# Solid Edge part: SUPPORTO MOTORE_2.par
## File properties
Subject: SUPPORTO MOTORE_2
Author: f_grande
Template: Normal.par
Last saved by: f_grande
Revision: 5
Application: Solid Edge
Material: Alluminio, 1060
Stile della faccia: Alluminio
Stile di riempimento: ANSI38(Alluminio)
Stile virtuale: Alluminio lucidato
Coef. of Thermal Exp: 0.0
Thermal Conductivity: 221.0
Specific Heat: 920.0
Modulus of Elasticity: 68947570000.0
Poisson's Ratio: 0.33
Yield Stress: 27579028.0
Ultimate Stress: 68947570.0
Elongation: 0.0
Tipo di contenuto documento: 0
Densità: 2712,000 kg/m^3
Precisione: 0,990
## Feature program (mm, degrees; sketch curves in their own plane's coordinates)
sketch for "unnamed Protrusion 1" plane through (0, 0, 0) normal (0, 0, 1) x-axis (1, 0, 0)
  line (-30, 7.5) -> (30, 7.5)
  line (30, 7.5) -> (30, -7.5)
  line (30, -7.5) -> (-30, -7.5)
  line (-30, -7.5) -> (-30, 7.5)
  dimension (linear) = 30
extrude "unnamed Protrusion 1" add finite 80 symmetric
sketch for "Foro_7" plane through (0, 0, -40) normal (0, 0, -1) x-axis (0, -1, 0)
  hole centre (-1.07, -23.57) bore radius 1.621
hole "Foro_7" nominal diameter 4 finite
sketch for "unnamed Hole 1" plane through (0, 0, -40) normal (0, 0, -1) x-axis (0, -1, 0)
  hole centre (-1.07, 23.57) bore radius 1.621
hole "unnamed Hole 1" finite
sketch for "Foro_9" plane through (0, 0, 40) normal (0, 0, 1) x-axis (1, 0, 0)
  hole centre (23.57, 1.07) bore radius 1.621
hole "Foro_9" nominal diameter 4 finite
sketch for "unnamed Hole 2" plane through (0, 0, 40) normal (0, 0, 1) x-axis (1, 0, 0)
  hole centre (-23.57, 1.07) bore radius 1.621
  dimension (linear) = 23.57
hole "unnamed Hole 2" finite
pattern "unnamed Pattern 1" of "Foro_7", "unnamed Hole 1"
pattern "unnamed Pattern 2" of "Foro_9", "unnamed Hole 2"
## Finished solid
Body 1: solid body, 14 faces, 20 edges, 8 vertices.
  Faces by surface: plane 10, cylinder 4
  Edges by curve: line 12, circle 8
Bounding box of the edges (mm): 60.000 x 15.000 x 80.000, from (-30, -7.5, -40) to (30, 7.5, 40).
Cylindrical faces by radius (mm): R1.621 x4
Planar faces by outward normal: +x 1, +y 1, +z 3, -x 1, -y 1, -z 3
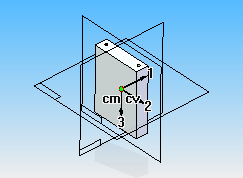
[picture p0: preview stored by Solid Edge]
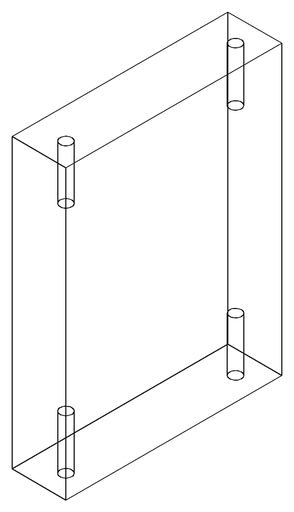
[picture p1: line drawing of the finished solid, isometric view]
